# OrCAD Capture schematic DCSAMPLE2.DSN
size A
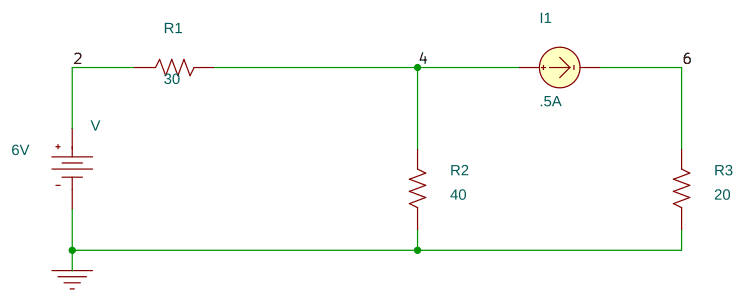
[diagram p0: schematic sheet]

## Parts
I1  IDC
R1  30  [AX/RC05]
R2  40  [AX/RC05]
R3  20  [AX/RC05]
V  VDC

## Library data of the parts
I1 = IDC: DC: .5A
R1-R3 = R
V = VDC: DC: 6V

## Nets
0: R2.1 R3.1 V.1(-)
2: R1.1 V.0(+)
4: I1.1(+) R1.2 R2.2
6: I1.2(-) R3.2
